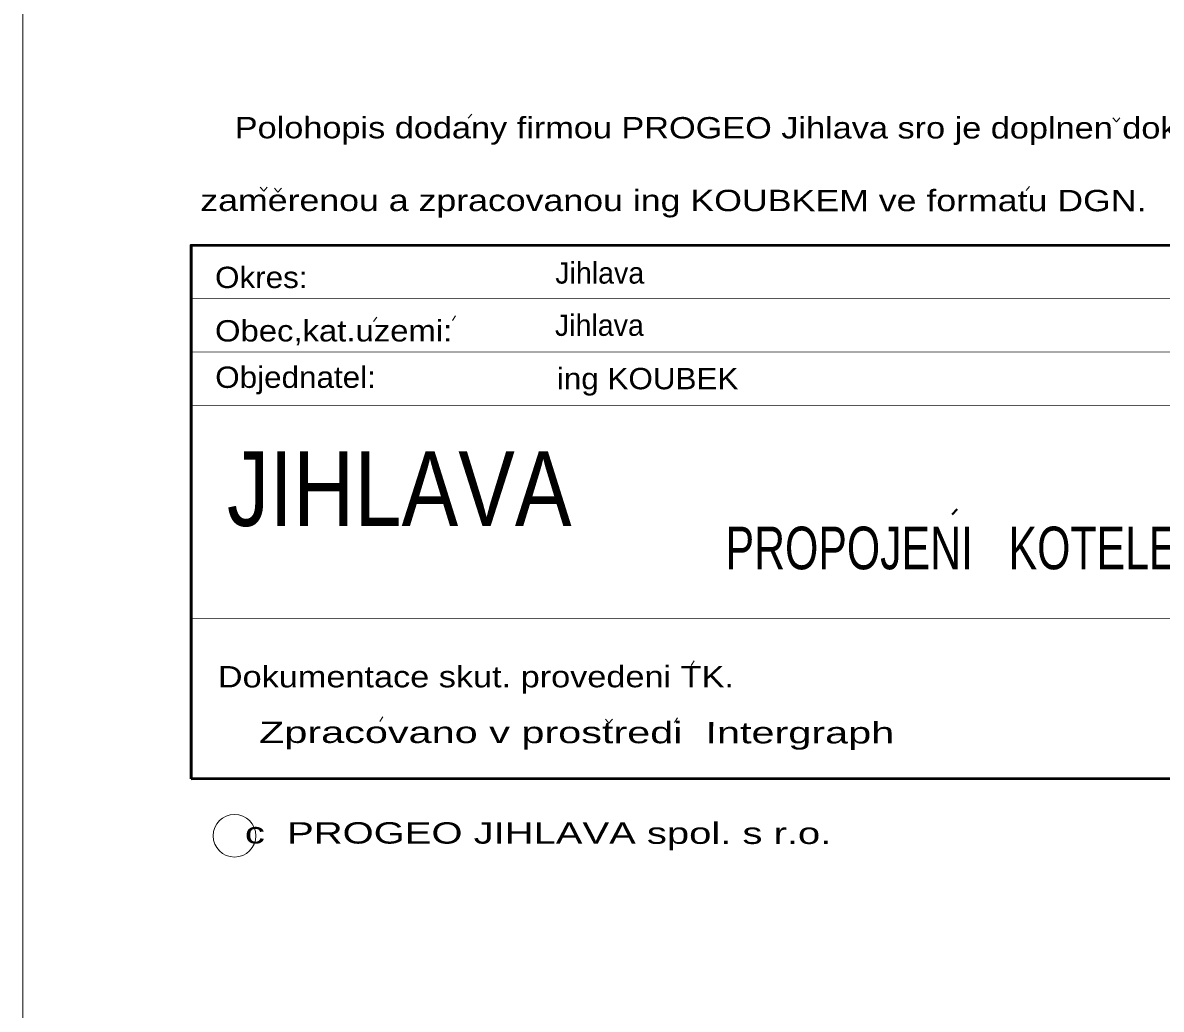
# Model space of a CAD drawing. Extents: x -670514 to -669423, y -1130798 to -1130123.
# Drawn here: x -670405.55 to -670362.9, y -1130272.33 to -1130235.35 of the extents above; entities that cross this region are included whole.
import ezdxf
from ezdxf.enums import TextEntityAlignment as Align

# ---------------------------------------------------------------- set-up
doc = ezdxf.new("R2010")
doc.units = 0
doc.header["$LTSCALE"] = 0.24
doc.layers.add('60', color=7, linetype='Continuous', lineweight=13)
doc.layers.add('61', color=7, linetype='Continuous', lineweight=13)

msp = doc.modelspace()

# ---------------------------------------------------------------- linework, layer by layer
at = {"layer": '60'}
msp.add_lwpolyline([(-670405.553, -1130409.706), (-669995.553, -1130409.706), (-669995.553, -1130122.706), (-670405.553, -1130122.706)], close=True, dxfattribs=at)
at = {"layer": '61'}
for p, q in [((-670388.731, -1130238.78), (-670388.864, -1130238.931)), ((-670364.711, -1130238.914), (-670364.578, -1130239.063)), ((-670364.444, -1130238.912), (-670364.578, -1130239.063)), ((-670396.654, -1130241.52), (-670396.522, -1130241.668)), ((-670396.39, -1130241.518), (-670396.522, -1130241.668)), ((-670396.127, -1130241.553), (-670395.995, -1130241.701)), ((-670395.863, -1130241.551), (-670395.995, -1130241.701)), ((-670367.828, -1130241.491), (-670367.962, -1130241.639)), ((-670399.251, -1130245.699), (-670359.246, -1130245.686)), ((-670392.412, -1130246.557), (-670392.293, -1130246.385)), ((-670389.454, -1130246.512), (-670389.339, -1130246.335)), ((-670399.251, -1130247.7), (-670359.251, -1130247.689)), ((-670399.248, -1130249.695), (-670359.248, -1130249.687)), ((-670399.248, -1130257.699), (-670359.25, -1130257.689)), ((-670380.515, -1130259.453), (-670380.399, -1130259.276)), ((-670392.172, -1130261.542), (-670392.057, -1130261.367)), ((-670383.723, -1130261.458), (-670383.59, -1130261.608)), ((-670383.457, -1130261.46), (-670383.59, -1130261.608)), ((-670381.131, -1130261.583), (-670381.016, -1130261.406))]:
    msp.add_line(p, q, dxfattribs=at)
at = {"layer": '61', "lineweight": 40}
msp.add_line((-670370.725, -1130253.79), (-670370.539, -1130253.585), dxfattribs=at)
at = {"layer": '61', "lineweight": 53}
msp.add_lwpolyline([(-670399.245, -1130263.7), (-670339.248, -1130263.681), (-670339.249, -1130243.684), (-670399.248, -1130243.696)], close=True, dxfattribs=at)
at = {"layer": '61'}
msp.add_circle((-670397.6224, -1130265.8279), 0.8, dxfattribs=at)

# ---------------------------------------------------------------- texts
for s, height, rotation, width, p in [('Polohopis dodany firmou PROGEO Jihlava sro je doplnen dokumentaci TK', 0.8, 359.983, 1.2, (-670376.3451, -1130239.6887)), ('zamerenou a zpracovanou ing KOUBKEM ve formatu DGN.', 0.8, 359.983, 1.25, (-670381.1746, -1130242.4133)), ('JIHLAVA', 2.8, 0.009, 0.85, (-670391.4477, -1130254.2169)), ('Zpracovano v prostredi  Intergraph', 0.8, 359.948, 1.45, (-670384.8009, -1130262.3591)), ('c  PROGEO JIHLAVA spol. s r.o.', 0.8, 359.948, 1.4, (-670386.2454, -1130266.1286))]:
    msp.add_text(s, height=height, rotation=rotation, dxfattribs=dict(at, width=width)).set_placement(p, align=Align.CENTER)
for p in [(-670385.6, -1130245.131), (-670385.613, -1130247.09)]:
    msp.add_text('Jihlava', height=0.8, rotation=0.015, dxfattribs=at).set_placement(p)
for s, height, rotation, width, p in [('Okres:', 0.8, 0.014, 1.1, (-670398.348, -1130245.297)), ('Obec,kat.uzemi:', 0.8, 0.014, 1.15, (-670398.351, -1130247.3)), ('Objednatel:', 0.8, 0.014, 1.1, (-670398.342, -1130249.04)), ('ing KOUBEK', 0.8, 0.015, 1.1, (-670385.542, -1130249.092)), ('PROPOJENI   KOTELEN', 1.599, 0.009, 0.75, (-670379.22, -1130255.841)), ('Dokumentace skut. provedeni TK.', 0.8, 0.015, 1.2, (-670398.243, -1130260.268))]:
    msp.add_text(s, height=height, rotation=rotation, dxfattribs=dict(at, width=width)).set_placement(p)

doc.saveas('drawing.dxf')
